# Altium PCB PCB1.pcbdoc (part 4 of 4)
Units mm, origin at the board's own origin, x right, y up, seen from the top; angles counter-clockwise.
Board outline 94.87 x 122.3 mm, 4 copper layers (Top Layer, Inner1, Inner2, Bottom Layer); 129 components, 127 nets, 714 pads, 326 vias.
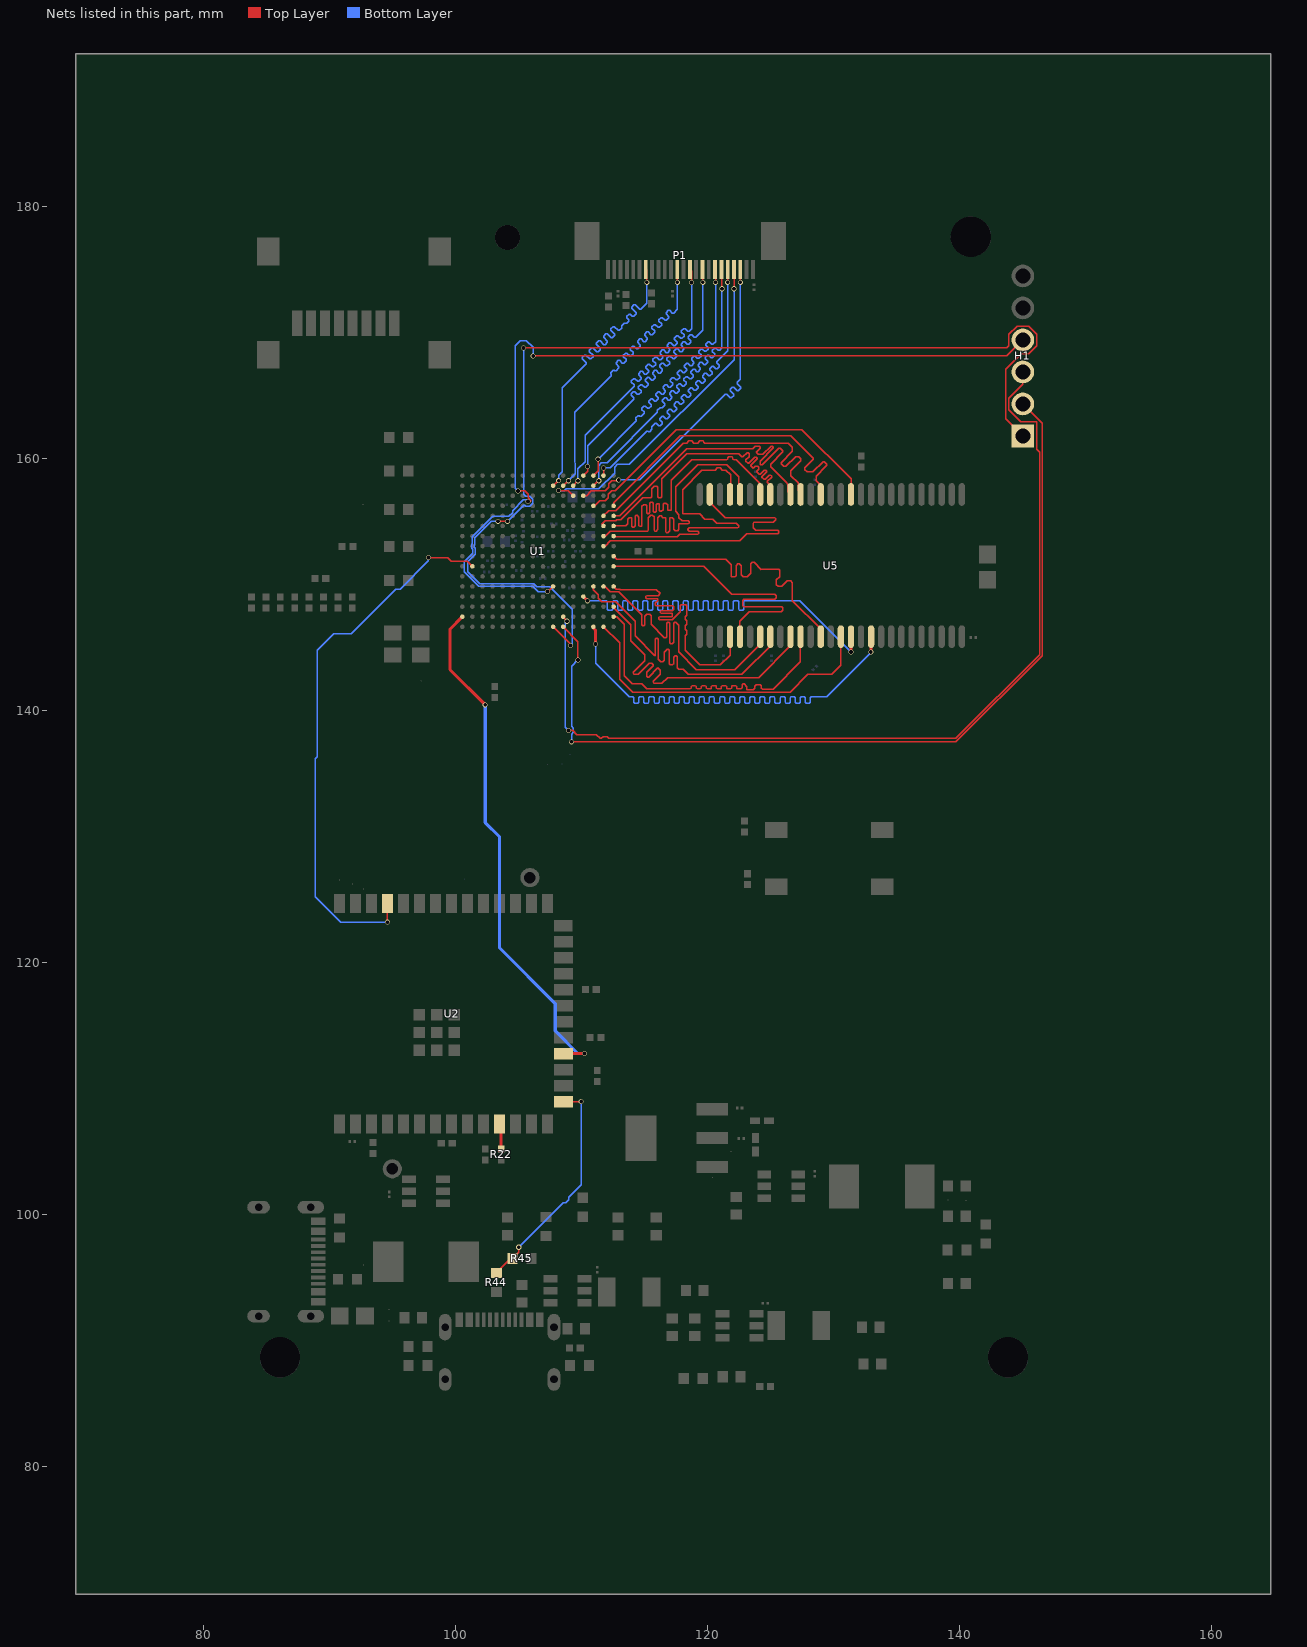
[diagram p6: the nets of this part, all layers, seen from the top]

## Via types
v1: diameter 0.4, hole 0.3, Top Layer to Bottom Layer, 311 vias
v2: diameter 1, hole 0.5, Top Layer to Bottom Layer, 12 vias
v3: diameter 0.5, hole 0.3, Top Layer to Bottom Layer, 3 vias

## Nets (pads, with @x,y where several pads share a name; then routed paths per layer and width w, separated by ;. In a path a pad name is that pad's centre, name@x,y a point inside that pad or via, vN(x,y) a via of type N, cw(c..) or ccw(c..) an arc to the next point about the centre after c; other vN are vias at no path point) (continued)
SD_DQ1: U1.M16 U5.4 | length 25
  Top Layer w0.1: U1.M16@112.553,149.854 112.769,149.638 113.03,149.638 113.068,149.6 115.957,149.6 116.258,149.299 116.087,149.127 115.189,149.127 115.118,149.056 115.118,148.956 115.189,148.886 116.036,148.886 116.078,148.844 116.078,148.705 115.88,148.508 115.88,148.408 115.951,148.337 117.22,148.337 117.327,148.23 117.327,148.061 117.2,147.934 116.332,147.934 116.267,147.869 116.267,147.777 116.332,147.713 117.22,147.713 117.22,147.479 117.203,147.461 116.205,147.461 116.134,147.391 116.134,147.291 116.205,147.22 117.22,147.22 117.856,147.856 117.856,148.336 117.927,148.407 118.293,148.407 118.364,148.336 118.364,147.574 118.237,147.447 118.237,147.243 118.357,147.123 118.357,146.843 118.237,146.723 118.237,146.443 118.357,146.323 118.357,146.043 118.237,145.923 118.237,144.78 119.38,143.637 121.031,143.637 121.794,144.4 U5.4@121.794,145.996
SD_DQ2: U1.K16 U5.5 | length 25.6
  Top Layer w0.1: U1.K16@112.553,151.454 119.691,151.454 121.92,149.225 125.349,149.225 125.476,149.098 125.476,148.971 125.333,148.828 122.901,148.828 122.791,148.717 122.791,148.313 122.851,148.253 125.913,148.253 125.984,148.182 125.984,147.955 125.858,147.829 123.318,147.829 122.577,147.088 122.577,146.267 122.594,146.25 U5.5@122.594,145.996
SD_DQ3: U1.M15 U5.7 | length 24.8
  Top Layer w0.1: U1.M15@111.753,149.854 111.833,149.854 111.847,149.839 111.895,149.839 112.298,149.436 112.946,149.436 114.793,147.589 114.793,146.812 114.863,146.741 114.963,146.741 115.034,146.812 115.034,147.489 115.189,147.644 115.443,147.644 115.543,147.544 115.543,146.839 116.586,145.796 116.713,145.796 116.771,145.854 116.771,146.939 116.842,147.01 116.942,147.01 117.012,146.939 117.012,145.37 117.094,145.288 117.221,145.288 117.345,145.412 117.345,146.939 117.404,146.998 117.487,146.998 117.709,146.776 117.709,144.673 119.126,143.256 122.179,143.256 124.05,145.127 124.05,145.725 124.067,145.742 124.067,145.869 U5.7@124.194,145.996
SD_DQ4: U1.M14 U5.8 | length 25.8
  Top Layer w0.1: U1.M14@110.953,149.854 110.953,149.594 111.335,149.212 111.335,148.932 111.631,148.636 112.711,148.636 114.273,147.074 114.273,145.923 115.831,144.365 115.863,144.397 115.863,145.669 115.934,145.74 116.034,145.74 116.104,145.669 116.104,144.092 116.305,143.891 116.459,143.891 116.578,144.01 116.578,144.632 116.796,144.851 116.896,144.851 116.967,144.78 116.967,143.737 117.067,143.637 117.221,143.637 117.313,143.729 117.313,144.225 117.431,144.343 117.531,144.343 117.602,144.272 117.602,143.405 117.729,143.278 118.069,143.278 118.472,142.875 122.743,142.875 125.151,145.283 125.151,145.839 U5.8@124.994,145.996
SD_DQ5: U1.P16 U5.10 | length 25.6
  Top Layer w0.1: U1.P16@112.553,148.254 112.553,148.145 113.898,146.8 113.898,145.563 115.032,144.429 115.032,143.975 114.102,143.046 114.102,142.946 114.173,142.875 114.493,142.875 115.382,143.764 115.57,143.764 115.697,143.637 115.697,143.571 115.176,143.051 115.176,142.735 115.247,142.665 115.347,142.665 116.072,143.389 116.241,143.22 116.241,142.898 115.69,142.347 115.69,142.247 115.761,142.176 116.395,142.176 116.84,142.621 124.071,142.621 126.594,145.144 U5.10@126.594,145.996
SD_DQ6: U1.R16 U5.11 | length 25.2
  Top Layer w0.1: U1.R16@112.553,147.454 112.817,147.454 113.411,146.86 113.411,142.748 114.042,142.117 114.804,142.117 115.205,141.716 118.647,141.716 118.717,141.787 118.717,141.915 118.788,141.986 119.047,141.986 119.117,141.915 119.117,141.787 119.188,141.716 119.447,141.716 119.517,141.787 119.517,141.915 119.588,141.986 119.847,141.986 119.917,141.915 119.917,141.787 119.988,141.716 120.247,141.716 120.317,141.787 120.317,141.915 120.388,141.986 120.647,141.986 120.717,141.915 120.717,141.787 120.788,141.716 121.047,141.716 121.117,141.787 121.117,141.915 121.188,141.986 121.447,141.986 121.517,141.915 121.517,141.787 121.588,141.716 121.847,141.716 121.917,141.787 121.917,141.915 121.988,141.986 122.247,141.986 122.317,141.915 122.317,141.787 122.388,141.716 122.665,141.716 122.765,141.816 122.765,142.042 122.836,142.113 122.936,142.113 123.142,141.907 123.142,141.656 123.654,141.656 123.754,141.756 123.754,141.915 123.881,142.042 124.206,142.042 124.277,141.972 124.277,141.786 124.377,141.686 125.208,141.686 127.381,143.859 U5.11@127.381,145.491
SD_DQ7: U1.J16 U5.13 | length 25.2
  Top Layer w0.1: U1.J16@112.553,152.254 112.788,152.019 121.44,152.019 121.876,151.582 121.876,150.68 121.947,150.609 122.188,150.609 122.288,150.709 122.288,151.511 122.425,151.647 122.546,151.647 122.684,151.509 122.684,150.774 122.849,150.609 123.177,150.609 123.46,150.892 123.46,151.654 123.571,151.765 123.714,151.765 124.282,151.197 124.286,151.201 125.659,151.201 125.73,151.13 125.73,150.631 125.476,150.377 125.476,150.003 125.619,149.86 125.916,149.86 126.351,150.296 126.619,150.296 126.748,150.166 126.748,148.732 ; 126.748,148.731 128.994,146.485 U5.13@128.994,145.996
SD_DQ8: U1.D16 U5.42 | length 25.2
  Top Layer w0.1: U1.D16@112.553,156.254 112.553,156.508 117.843,161.798 126.619,161.798 128.397,160.02 128.397,159.939 127.741,159.283 127.741,159.131 127.929,158.943 128.363,158.943 129.186,159.766 129.286,159.766 129.484,159.568 129.484,159.456 129.413,159.385 129.407,159.385 128.63,158.608 128.63,158.242 128.867,158.005 128.867,157.407 U5.42@128.994,157.28
SD_DQ9: U1.E15 U5.44 | length 25
  Top Layer w0.1: U1.E15@111.753,155.454 112.171,155.872 112.711,155.872 118.066,161.226 118.366,161.226 118.436,161.297 118.436,161.346 118.507,161.417 118.766,161.417 118.836,161.346 118.836,161.297 118.907,161.226 119.252,161.226 119.323,161.297 119.323,161.346 119.394,161.417 119.652,161.417 119.723,161.346 119.723,161.297 119.794,161.226 126.428,161.226 126.746,160.909 126.746,160.57 125.857,159.681 125.857,159.573 126.045,159.385 126.238,159.385 127,160.147 127.254,160.147 127.423,159.978 127.423,159.836 126.619,159.032 126.619,158.653 127.203,158.069 127.203,157.471 U5.44@127.394,157.28
SD_DQ10: U1.E16 U5.45 | length 25
  Top Layer w0.1: U1.E16@112.553,155.454 113.036,155.454 118.364,160.782 123.581,160.782 123.779,160.98 124.135,160.98 124.206,160.909 124.206,160.823 123.873,160.49 124.031,160.332 124.404,160.332 125.051,160.98 125.151,160.98 125.222,160.909 125.222,160.842 124.176,159.796 124.176,159.569 124.247,159.498 124.347,159.498 125.68,160.832 125.78,160.832 125.984,160.628 125.984,160.528 125.023,159.567 125.023,159.34 126.246,158.117 126.246,158.112 126.38,157.978 126.38,157.38 126.48,157.28 U5.45@126.594,157.28
SD_DQ11: U1.F15 U5.47 | length 25.1
  Top Layer w0.1: U1.F15@111.753,154.654 111.626,154.781 111.626,154.806 111.892,155.072 112.711,155.072 112.802,155.163 113.126,155.163 114.864,156.901 115.499,156.901 115.57,156.972 115.57,157.607 115.773,157.81 115.978,157.81 116.078,157.71 116.078,156.972 116.149,156.901 116.298,156.901 116.369,156.972 116.369,158.406 118.364,160.401 122.471,160.401 122.731,160.141 122.816,160.141 123.146,160.472 123.246,160.472 123.317,160.401 123.317,160.147 123.063,159.893 123.063,159.809 123.249,159.624 123.302,159.624 123.769,160.091 123.881,160.091 123.952,160.02 123.952,159.975 123.444,159.467 123.444,159.428 123.644,159.229 123.8,159.385 124.016,159.385 124.079,159.322 124.079,159.162 123.921,159.004 123.921,158.951 124.122,158.75 124.206,158.75 124.531,159.075 124.643,159.075 124.714,159.004 124.714,158.955 124.333,158.574 124.333,158.539 124.528,158.344 124.575,158.344 124.924,158.694 125.024,158.694 125.095,158.623 125.095,158.525 124.757,158.187 124.757,158.115 124.994,157.878 U5.47@124.994,157.28
SD_DQ12: U1.F16 U5.48 | length 25.1
  Top Layer w0.1: U1.F16@112.553,154.654 113.506,154.654 113.665,154.813 113.665,155.194 113.792,155.321 113.959,155.321 114.002,155.277 114.002,154.63 114.073,154.559 114.173,154.559 114.281,154.667 114.281,155.429 114.339,155.487 114.427,155.487 114.562,155.352 114.562,154.69 114.637,154.615 114.737,154.615 114.808,154.686 114.808,156.21 114.935,156.337 115.121,156.337 115.202,156.257 115.202,155.702 115.272,155.631 115.341,155.631 115.443,155.734 115.443,156.459 115.506,156.522 115.639,156.522 115.71,156.451 115.71,155.829 115.78,155.758 115.88,155.758 115.951,155.829 115.951,156.337 116.015,156.401 116.141,156.401 116.176,156.366 116.176,155.885 116.247,155.814 116.347,155.814 116.488,155.956 116.488,156.366 116.586,156.464 116.713,156.464 116.84,156.337 116.84,155.956 116.911,155.885 117.079,155.885 117.15,155.956 117.15,158.298 118.745,159.893 121.554,159.893 121.624,159.964 121.624,160.076 121.695,160.147 121.954,160.147 122.024,160.076 122.024,159.964 122.095,159.893 122.301,159.893 124.136,158.058 124.136,157.38 124.194,157.322 U5.48@124.194,157.28
SD_DQ13: U1.G15 U5.50 | length 25.1
  Top Layer w0.1: U1.G15@111.753,153.854 111.894,153.854 112.276,154.236 115.247,154.236 115.316,154.305 115.316,155.321 115.499,155.504 115.641,155.504 115.768,155.377 115.768,154.305 115.838,154.234 115.938,154.234 116.078,154.374 116.078,155.321 116.205,155.448 116.332,155.448 116.459,155.321 116.675,155.321 116.675,154.178 116.746,154.107 116.846,154.107 117.005,154.267 117.005,155.264 117.062,155.321 117.221,155.321 117.348,155.194 117.348,154.378 117.448,154.278 117.629,154.278 117.729,154.378 117.729,154.771 117.771,154.813 118.491,154.813 118.562,154.884 118.562,154.984 118.483,155.062 117.988,155.062 117.729,155.321 117.729,155.562 117.487,155.805 117.487,157.752 119.247,159.512 121.539,159.512 122.476,158.575 122.476,157.399 U5.50@122.594,157.28
SD_DQ14: U1.G16 U5.51 | length 25
  Top Layer w0.1: U1.G16@112.553,153.854 112.616,153.79 117.595,153.79 117.789,153.984 119.253,153.984 119.324,154.055 119.324,154.155 119.253,154.225 118.571,154.225 118.458,154.338 118.458,154.399 118.553,154.494 122.428,154.494 122.499,154.564 122.499,154.664 122.279,154.884 120.733,154.884 120.423,155.194 119.799,155.194 119.38,155.613 118.03,155.613 118.03,157.527 119.57,159.067 120.634,159.067 120.705,159.138 120.705,159.212 120.775,159.283 121.034,159.283 121.105,159.212 121.105,159.138 121.176,159.067 121.475,159.067 121.84,158.703 121.84,157.615 U5.51@121.858,157.598
SD_DQ15: U1.H15 U5.53 | length 25.3
  Top Layer w0.1: U1.H15@111.753,153.054 111.88,153.054 112.298,153.472 122.584,153.472 123.141,154.029 125.569,154.029 125.674,154.134 125.674,154.234 125.603,154.305 123.825,154.305 123.627,154.503 123.627,154.869 123.698,154.94 125.209,154.94 125.42,155.15 125.42,155.25 125.349,155.321 121.412,155.321 120.321,156.412 U5.53@120.321,157.153
SD_DQM0: U1.T15 U5.15 | length 25.8
  Top Layer w0.1: U1.T15@111.753,146.654 113.03,145.377 113.03,142.494 114.068,141.456 126.563,141.456 127.982,142.875 129.881,142.875 130.594,143.588 U5.15@130.594,145.869
SD_DQM1: U1.D14 U5.39 | length 25.9
  Top Layer w0.1: U1.D14@110.953,156.254 111.042,156.254 111.46,156.672 111.911,156.672 112.135,156.896 112.135,157.176 112.395,157.436 112.675,157.436 117.545,162.306 127.492,162.306 131.403,158.396 131.403,157.407 U5.39@131.276,157.28
SD_RAS_N: U1.T14 U5.18 | length 43.8
  Top Layer w0.254: U1.T14@110.998,146.488 111.125,146.361 v1(111.125,145.288) ; v1(132.969,144.653) 132.994,144.678 U5.18@132.994,145.869
  Bottom Layer w0.1: v1(111.125,145.288) 111.125,143.764 113.792,141.097 114.092,141.097 114.163,141.026 114.163,140.66 114.233,140.589 114.492,140.589 114.563,140.66 114.563,141.026 114.633,141.097 114.892,141.097 114.963,141.026 114.963,140.66 115.033,140.589 115.292,140.589 115.363,140.66 115.363,141.026 115.433,141.097 115.692,141.097 115.763,141.026 115.763,140.66 115.833,140.589 116.092,140.589 116.163,140.66 116.163,141.026 116.233,141.097 116.492,141.097 116.563,141.026 116.563,140.66 116.633,140.589 116.892,140.589 116.963,140.66 116.963,141.026 117.033,141.097 117.292,141.097 117.363,141.026 117.363,140.66 117.433,140.589 117.692,140.589 117.763,140.66 117.763,141.026 117.833,141.097 118.092,141.097 118.163,141.026 118.163,140.66 118.233,140.589 118.492,140.589 118.563,140.66 118.563,141.026 118.633,141.097 118.892,141.097 118.963,141.026 118.963,140.66 119.033,140.589 119.292,140.589 119.363,140.66 119.363,141.026 119.433,141.097 119.692,141.097 119.763,141.026 119.763,140.66 119.833,140.589 120.092,140.589 120.163,140.66 120.163,141.026 120.233,141.097 120.492,141.097 120.563,141.026 120.563,140.66 120.633,140.589 120.892,140.589 120.963,140.66 120.963,141.026 121.033,141.097 121.292,141.097 121.363,141.026 121.363,140.66 121.433,140.589 121.692,140.589 121.763,140.66 121.763,141.026 121.833,141.097 122.092,141.097 122.163,141.026 122.163,140.66 122.233,140.589 122.492,140.589 122.563,140.66 122.563,141.026 122.633,141.097 122.892,141.097 122.963,141.026 122.963,140.66 123.033,140.589 123.292,140.589 123.363,140.66 123.363,141.026 123.433,141.097 123.692,141.097 123.763,141.026 123.763,140.66 123.833,140.589 124.092,140.589 124.163,140.66 124.163,141.026 124.233,141.097 124.492,141.097 124.563,141.026 124.563,140.66 124.633,140.589 124.892,140.589 124.963,140.66 124.963,141.026 125.033,141.097 125.292,141.097 125.363,141.026 125.363,140.66 125.433,140.589 125.692,140.589 125.763,140.66 125.763,141.026 125.833,141.097 126.092,141.097 126.163,141.026 126.163,140.66 126.233,140.589 126.492,140.589 126.563,140.66 126.563,141.026 126.633,141.097 126.892,141.097 126.963,141.026 126.963,140.66 127.033,140.589 127.292,140.589 127.363,140.66 127.363,141.026 127.433,141.097 127.692,141.097 127.763,141.026 127.763,140.66 127.833,140.589 128.092,140.589 128.163,140.66 128.163,141.026 128.233,141.097 129.461,141.097 132.969,144.605 v1(132.969,144.653)
SD_WE_N: U1.N13 U5.16 | length 43.3
  Top Layer w0.254: U1.N13@110.153,149.054 v1(110.49,148.717) ; v1(131.394,144.653) U5.16@131.394,145.869
  Bottom Layer w0.1: v1(110.49,148.717) 111.998,148.717 112.069,148.646 112.069,148.026 112.14,147.955 112.398,147.955 112.469,148.026 112.469,148.646 112.54,148.717 112.798,148.717 112.869,148.646 112.869,148.026 112.94,147.955 113.198,147.955 113.269,148.026 113.269,148.646 113.34,148.717 113.598,148.717 113.669,148.646 113.669,148.026 113.74,147.955 113.998,147.955 114.069,148.026 114.069,148.646 114.14,148.717 114.398,148.717 114.469,148.646 114.469,148.026 114.54,147.955 114.798,147.955 114.869,148.026 114.869,148.646 114.94,148.717 115.198,148.717 115.269,148.646 115.269,148.026 115.34,147.955 115.598,147.955 115.669,148.026 115.669,148.646 115.74,148.717 115.998,148.717 116.069,148.646 116.069,148.026 116.14,147.955 116.398,147.955 116.469,148.026 116.469,148.646 116.54,148.717 116.798,148.717 116.869,148.646 116.869,148.026 116.94,147.955 117.198,147.955 117.269,148.026 117.269,148.646 117.34,148.717 117.598,148.717 117.669,148.646 117.669,148.026 117.74,147.955 117.998,147.955 118.069,148.026 118.069,148.646 118.14,148.717 118.398,148.717 118.469,148.646 118.469,148.026 118.54,147.955 118.798,147.955 118.869,148.026 118.869,148.646 118.94,148.717 119.198,148.717 119.269,148.646 119.269,148.026 119.34,147.955 119.598,147.955 119.669,148.026 119.669,148.646 119.74,148.717 119.998,148.717 120.069,148.646 120.069,148.026 120.14,147.955 120.398,147.955 120.469,148.026 120.469,148.646 120.54,148.717 120.798,148.717 120.869,148.646 120.869,148.026 120.94,147.955 121.198,147.955 121.269,148.026 121.269,148.646 121.34,148.717 121.598,148.717 121.669,148.646 121.669,148.026 121.74,147.955 121.998,147.955 122.069,148.026 122.069,148.646 122.14,148.717 122.398,148.717 122.469,148.646 122.469,148.026 122.54,147.955 122.798,147.955 122.869,148.026 122.869,148.646 122.94,148.717 127.33,148.717 v1(131.394,144.653)
SDA: R22.1 U2.11 | length 1.9
  Top Layer w0.254: R22.1@103.627,105.283 U2.11@103.627,107.201
SSPI_CS_N: U1.R1 U2.18 | length 41.3
  Top Layer w0.254: U1.R1@100.553,147.454 99.568,146.469 99.568,143.256 v1(102.362,140.462) ; U2.18@108.717,112.776 v1(110.236,112.776)
  Bottom Layer w0.254: v1(102.362,140.462) 102.362,131.108 103.505,129.965 103.505,121.158 107.923,116.74 107.923,114.581 109.728,112.776 v1(110.236,112.776)
TCK: H1.1 U1.T10 | length 88.4
  Top Layer w0.1: v1(103.374,155.026) 103.585,155.026 103.595,155.036 103.911,155.036 103.921,155.026 104.099,155.026 v1@104.14,155.067 ; v1(105.41,168.783) 143.748,168.783 143.932,168.967 143.932,169.874 144.578,170.52 145.49,170.52 146.136,169.874 146.136,168.962 145.49,168.316 144.914,168.316 143.681,167.084 143.681,163.151 H1.1@145.034,161.798 ; U1.T10@107.753,146.654 109.137,145.27 v1(109.137,145.161)
  Bottom Layer w0.1: v1(103.374,155.026) 102.858,155.026 101.555,153.723 101.555,153.167 101.506,153.117 101.506,152.965 101.567,152.903 101.567,152.405 100.965,151.803 100.965,151.032 101.937,150.06 106.236,150.06 106.449,149.846 107.482,149.846 109.268,148.06 109.268,145.292 v1(109.137,145.161) ; v1(104.14,155.026) 105.41,156.296 105.495,156.296 105.587,156.204 105.92,156.204 106.155,156.44 106.155,156.773 105.92,157.008 105.587,157.008 105.41,157.185 v1(105.41,168.783)
TDI: H1.3 U1.R11 | length 74.5
  Top Layer w0.1: U1.R11@108.553,147.454 108.553,147.406 v1(108.866,147.093) ; v1(108.966,138.43) 109.294,138.43 109.621,138.103 111.171,138.103 111.479,137.795 111.593,137.795 111.72,137.922 112.054,137.922 112.181,137.795 139.7,137.795 146.358,144.453 146.358,160.518 146.145,160.731 146.145,162.944 144.869,162.944 143.932,163.882 143.932,164.794 145.034,165.896 H1.3@145.034,166.878
  Bottom Layer w0.1: v1(108.866,147.093) 108.735,146.962 108.735,138.661 v1(108.966,138.43)
TDO: H1.4 U1.M10 | length 72.1
  Top Layer w0.1: v1(104.965,157.419) 105.177,157.419 105.195,157.436 105.511,157.436 105.771,157.176 105.771,156.896 105.995,156.672 105.995,156.636 105.965,156.606 v1(105.753,156.606) ; v1(106.172,168.148) 143.764,168.148 H1.4@145.034,169.418 ; v1(107.315,149.444) 107.343,149.444 U1.M10@107.753,149.854
  Bottom Layer w0.1: v1(104.965,157.419) 104.754,157.63 104.754,168.966 105.154,169.366 105.635,169.366 106.172,168.829 v1(106.172,168.148) ; v1(105.753,156.606) 105.626,156.733 105.397,156.733 104.542,155.879 104.542,155.722 104.248,155.428 102.977,155.428 101.355,153.806 101.355,153.249 101.306,153.2 101.306,152.882 101.367,152.821 101.367,152.487 100.711,151.831 100.711,151.003 101.854,149.86 106.153,149.86 106.568,149.444 v1(107.315,149.444)
TMS: H1.2 U1.T11 | length 70.7
  Top Layer w0.1: U1.T11@108.553,146.654 109.728,145.479 v1(109.728,144.018) ; v1(109.22,137.52) 139.708,137.52 146.558,144.37 146.558,162.814 H1.2@145.034,164.338
  Bottom Layer w0.1: v1(109.22,137.52) 109.22,138.115 109.368,138.263 109.368,138.597 109.22,138.745 109.22,143.51 v1(109.728,144.018)
TX: U1.K2 U2.37 | length 43.6
  Top Layer w0.1: v1@94.61,123.19 U2.37@94.61,124.701 ; v1@97.79,152.146 99.38,152.146 99.655,151.871 100.934,151.871 ; 100.935,151.872 U1.K2@101.353,151.454
  Bottom Layer w0.1: v1(94.61,123.211) 90.911,123.211 88.877,125.245 88.877,136.174 89.027,136.324 89.027,144.78 90.351,146.104 91.723,146.104 95.258,149.639 95.626,149.639 97.865,151.878 v1(97.865,152.146)
USB_VBUS: R44.1 R45.2 U2.15 | length 18
  Top Layer w0.1: R44.1@103.251,95.368 104.403,96.52 R45.2@104.53,96.52 105.029,97.019 v1(105.029,97.409) ; U2.15@108.59,108.966 v1(109.982,108.966)
  Bottom Layer w0.1: v1(105.029,97.409) 108.555,100.935 108.752,100.935 108.987,101.171 108.987,101.367 109.982,102.362 v1(109.982,108.966)
VSYNC: P1.7 U1.B10 | length 27.1
  Top Layer w0.1: U1.B10@107.753,157.854 108.149,158.25 v1(108.196,158.25) ; P1.7@115.11,175.02 115.189,174.942 v1(115.189,173.99)
  Bottom Layer w0.1: v1(108.196,158.25) 108.196,158.682 108.479,158.964 108.479,165.629 110.374,167.524 110.374,167.624 110.065,167.933 110.065,168.033 110.248,168.216 110.348,168.216 110.657,167.907 110.757,167.907 110.94,168.09 110.94,168.19 110.631,168.499 110.631,168.599 110.813,168.782 110.913,168.782 111.223,168.473 111.323,168.473 111.505,168.655 111.505,168.755 111.196,169.065 111.196,169.165 111.379,169.347 111.479,169.347 111.788,169.038 111.888,169.038 112.071,169.221 112.071,169.321 111.762,169.63 111.762,169.73 111.945,169.913 112.045,169.913 112.354,169.604 112.454,169.604 112.637,169.787 112.637,169.887 112.328,170.196 112.328,170.296 112.511,170.479 112.611,170.479 112.92,170.17 113.02,170.17 113.206,170.356 113.206,170.549 113.393,170.735 113.585,170.735 113.768,170.918 113.768,171.018 113.602,171.184 113.602,171.284 113.785,171.467 113.885,171.467 114.051,171.301 114.151,171.301 114.334,171.484 114.334,171.584 113.989,171.928 113.989,172.028 114.172,172.211 114.272,172.211 114.617,171.867 114.717,171.867 115.189,172.339 v1(115.189,173.99)
Y2: P1.19 U1.B14 | length 27
  Top Layer w0.1: U1.B14@110.953,157.854 111.341,158.242 v1(111.379,158.242) ; P1.19@121.11,175.02 121.158,174.972 v1(121.158,173.482)
  Bottom Layer w0.1: v1(111.379,158.242) 111.379,159.07 111.358,159.091 111.358,159.425 111.593,159.66 112.035,159.66 116.039,163.664 116.039,163.83 116.24,164.03 116.405,164.03 116.621,164.246 116.621,164.346 116.433,164.534 116.433,164.634 116.615,164.816 116.715,164.816 116.903,164.628 117.003,164.628 117.186,164.811 117.186,164.911 116.998,165.099 116.998,165.199 117.181,165.382 117.281,165.382 117.469,165.194 117.569,165.194 117.752,165.377 117.752,165.477 117.564,165.665 117.564,165.765 117.747,165.948 117.847,165.948 118.035,165.76 118.135,165.76 118.318,165.943 118.318,166.043 118.13,166.231 118.13,166.331 118.313,166.513 118.413,166.513 118.601,166.326 118.701,166.326 118.883,166.508 118.883,166.608 118.695,166.796 118.695,166.896 118.878,167.079 118.978,167.079 119.166,166.891 119.266,166.891 119.449,167.074 119.449,167.174 119.261,167.362 119.261,167.462 119.444,167.645 119.544,167.645 119.732,167.457 119.832,167.457 120.015,167.64 120.015,167.74 119.827,167.928 119.827,168.028 120.01,168.211 120.11,168.211 120.298,168.023 120.398,168.023 120.58,168.205 120.58,168.305 120.392,168.493 120.392,168.593 120.575,168.776 120.675,168.776 120.863,168.588 120.963,168.588 121.158,168.783 v1(121.158,173.482)
Y3: P1.21 U1.C12 | length 27
  Top Layer w0.1: v1(108.19,157.465) 108.942,157.465 U1.C12@109.353,157.054 ; v1(122.112,173.482) P1.21@122.112,175.017
  Bottom Layer w0.1: v1(108.19,157.465) 108.639,157.465 108.798,157.624 111.396,157.624 112.628,158.856 112.628,159.298 112.863,159.533 113.813,159.533 122.112,167.832 v1(122.112,173.482)
Y4: P1.22 U1.C13 | length 27
  Top Layer w0.1: U1.C13@110.153,157.054 110.413,157.054 110.795,157.436 111.875,157.436 112.171,157.732 112.171,158.012 112.395,158.236 112.887,158.236 v1(112.962,158.31) ; v1(122.612,173.99) P1.22@122.612,175.017
  Bottom Layer w0.1: v1(112.962,158.31) 114.622,158.31 121.417,165.105 121.517,165.105 121.798,164.824 121.898,164.824 122.081,165.007 122.081,165.107 121.8,165.388 121.8,165.488 121.983,165.671 122.083,165.671 122.364,165.39 122.464,165.39 122.647,165.573 122.647,165.673 122.366,165.954 122.366,166.054 122.612,166.3 v1(122.612,173.99)
Y5: P1.20 U1.A15 | length 27
  Top Layer w0.1: U1.A15@111.753,158.654 111.76,158.661 v1(111.76,159.258) ; v1(121.612,173.99) P1.20@121.612,175.017
  Bottom Layer w0.1: v1(111.76,159.258) 112.306,159.258 115.203,162.156 115.303,162.156 115.311,162.147 115.411,162.147 115.594,162.33 115.594,162.43 115.586,162.439 115.586,162.539 115.846,162.799 115.946,162.799 116.145,162.6 116.245,162.6 116.428,162.783 116.428,162.883 116.229,163.082 116.229,163.182 116.412,163.364 116.512,163.364 116.711,163.166 116.811,163.166 116.994,163.349 116.994,163.449 116.795,163.647 116.795,163.747 116.978,163.93 117.078,163.93 117.276,163.731 117.376,163.731 117.559,163.914 117.559,164.014 117.361,164.213 117.361,164.313 117.543,164.496 117.643,164.496 117.842,164.297 117.942,164.297 118.125,164.48 118.125,164.58 117.926,164.779 117.926,164.879 118.109,165.061 118.209,165.061 118.408,164.863 118.508,164.863 118.691,165.046 118.691,165.146 118.492,165.344 118.492,165.444 118.675,165.627 118.775,165.627 118.973,165.428 119.073,165.428 119.256,165.611 119.256,165.711 119.058,165.91 119.058,166.01 119.24,166.193 119.34,166.193 119.539,165.994 119.639,165.994 119.822,166.177 119.822,166.277 119.623,166.476 119.623,166.576 119.806,166.758 119.906,166.758 120.105,166.56 120.205,166.56 120.388,166.743 120.388,166.843 120.189,167.041 120.189,167.141 120.372,167.324 120.472,167.324 120.67,167.125 120.77,167.125 120.953,167.308 120.953,167.408 120.755,167.607 120.755,167.707 121.612,168.564 v1(121.612,173.99)
Y6: P1.18 U1.A14 | length 27.1
  Top Layer w0.1: U1.A14@110.953,158.654 111.318,159.019 v1(111.318,159.954) ; P1.18@120.61,175.02 120.65,174.98 v1(120.65,173.99)
  Bottom Layer w0.1: v1(111.318,159.954) 114.357,162.992 114.357,163.092 114.311,163.137 114.311,163.237 114.494,163.42 114.594,163.42 114.64,163.375 114.74,163.375 114.969,163.604 114.969,163.704 114.783,163.889 114.783,163.989 114.966,164.172 115.066,164.172 115.251,163.986 115.351,163.986 115.534,164.169 115.534,164.269 115.349,164.455 115.349,164.555 115.532,164.737 115.632,164.737 115.817,164.552 115.917,164.552 116.1,164.735 116.1,164.835 115.915,165.02 115.915,165.12 116.097,165.303 116.197,165.303 116.383,165.118 116.483,165.118 116.666,165.301 116.666,165.401 116.48,165.586 116.48,165.686 116.663,165.869 116.763,165.869 116.948,165.683 117.048,165.683 117.231,165.866 117.231,165.966 117.046,166.152 117.046,166.252 117.229,166.435 117.329,166.435 117.514,166.249 117.614,166.249 117.797,166.432 117.797,166.532 117.612,166.717 117.612,166.817 117.794,167 117.894,167 118.08,166.815 118.18,166.815 118.363,166.998 118.363,167.098 118.177,167.283 118.177,167.383 118.36,167.566 118.46,167.566 118.645,167.381 118.745,167.381 118.928,167.563 118.928,167.663 118.743,167.849 118.743,167.949 118.926,168.132 119.026,168.132 119.211,167.946 119.311,167.946 119.494,168.129 119.494,168.229 119.309,168.414 119.309,168.514 119.492,168.697 119.592,168.697 119.777,168.512 119.877,168.512 120.06,168.695 120.06,168.795 119.874,168.98 119.874,169.08 120.057,169.263 120.157,169.263 120.343,169.078 120.443,169.078 120.65,169.285 v1(120.65,173.99)
Y7: P1.16 U1.A13 | length 26.9
  Top Layer w0.1: U1.A13@110.153,158.654 110.49,158.991 v1(110.49,159.385) ; P1.16@119.61,175.019 119.634,174.995 v1(119.634,173.99)
  Bottom Layer w0.1: v1(110.49,159.385) 110.49,161.036 114.168,164.714 114.168,164.814 113.951,165.032 113.951,165.132 114.133,165.314 114.233,165.314 114.451,165.097 114.551,165.097 114.734,165.28 114.734,165.38 114.516,165.597 114.516,165.697 114.699,165.88 114.799,165.88 115.017,165.663 115.117,165.663 115.299,165.845 115.299,165.945 115.082,166.163 115.082,166.263 115.265,166.446 115.365,166.446 115.582,166.228 115.682,166.228 115.865,166.411 115.865,166.511 115.648,166.729 115.648,166.829 115.83,167.011 115.93,167.011 116.148,166.794 116.248,166.794 116.431,166.977 116.431,167.077 116.213,167.294 116.213,167.394 116.396,167.577 116.496,167.577 116.714,167.36 116.814,167.36 116.996,167.542 116.996,167.642 116.779,167.86 116.779,167.96 116.962,168.143 117.062,168.143 117.279,167.925 117.379,167.925 117.562,168.108 117.562,168.208 117.345,168.426 117.345,168.526 117.527,168.708 117.627,168.708 117.845,168.491 117.945,168.491 118.128,168.674 118.128,168.774 117.91,168.991 117.91,169.091 118.093,169.274 118.193,169.274 118.411,169.057 118.511,169.057 118.693,169.239 118.693,169.339 118.476,169.557 118.476,169.657 118.659,169.84 118.759,169.84 118.976,169.622 119.076,169.622 119.634,170.18 v1(119.634,173.99)
Y8: P1.14 U1.B12 | length 27
  Top Layer w0.1: U1.B12@109.353,157.854 109.728,158.229 v1(109.728,158.242) ; P1.14@118.611,175.02 118.741,174.889 v1(118.741,173.986)
  Bottom Layer w0.1: v1(109.728,158.242) 109.728,159.192 110.29,159.754 110.29,161.852 114.188,165.75 114.188,165.85 113.97,166.067 113.97,166.167 114.153,166.35 114.253,166.35 114.471,166.133 114.571,166.133 114.764,166.326 114.764,166.426 114.547,166.644 114.547,166.744 114.73,166.927 114.83,166.927 115.047,166.709 115.147,166.709 115.33,166.892 115.33,166.992 115.112,167.209 115.112,167.309 115.295,167.492 115.395,167.492 115.613,167.275 115.713,167.275 115.896,167.458 115.896,167.558 115.678,167.775 115.678,167.875 115.861,168.058 115.961,168.058 116.178,167.84 116.278,167.84 116.461,168.023 116.461,168.123 116.244,168.341 116.244,168.441 116.427,168.624 116.527,168.624 116.744,168.406 116.844,168.406 117.027,168.589 117.027,168.689 116.809,168.906 116.809,169.006 116.992,169.189 117.092,169.189 117.31,168.972 117.41,168.972 117.593,169.155 117.593,169.255 117.375,169.472 117.375,169.572 117.558,169.755 117.658,169.755 117.876,169.538 117.976,169.538 118.158,169.72 118.158,169.82 117.941,170.038 117.941,170.138 118.124,170.321 118.224,170.321 118.441,170.103 118.541,170.103 118.741,170.303 v1(118.741,173.986)
Y9: P1.12 U1.B11 | length 27
  Top Layer w0.1: U1.B11@108.553,157.854 108.941,158.242 v1(108.966,158.242) ; v1(117.611,173.99) P1.12@117.611,175.02
  Bottom Layer w0.1: v1(108.966,158.242) 109.528,158.804 109.528,159.651 109.453,159.726 109.453,163.682 112.365,166.594 112.365,166.694 112.338,166.721 112.338,166.821 112.521,167.004 112.621,167.004 112.648,166.977 112.748,166.977 112.974,167.203 112.974,167.303 112.757,167.521 112.757,167.621 112.94,167.804 113.04,167.804 113.257,167.586 113.357,167.586 113.54,167.769 113.54,167.869 113.322,168.086 113.322,168.186 113.505,168.369 113.605,168.369 113.823,168.152 113.923,168.152 114.106,168.335 114.106,168.435 113.888,168.652 113.888,168.752 114.071,168.935 114.171,168.935 114.389,168.718 114.489,168.718 114.671,168.9 114.671,169 114.454,169.218 114.454,169.318 114.637,169.501 114.737,169.501 114.954,169.283 115.054,169.283 115.237,169.466 115.237,169.566 115.02,169.784 115.02,169.884 115.202,170.066 115.302,170.066 115.52,169.849 115.62,169.849 115.803,170.032 115.803,170.132 115.585,170.349 115.585,170.449 115.768,170.632 115.868,170.632 116.086,170.415 116.186,170.415 116.368,170.597 116.368,170.697 116.151,170.915 116.151,171.015 116.334,171.198 116.434,171.198 116.651,170.98 116.751,170.98 116.934,171.163 116.934,171.263 116.717,171.481 116.717,171.581 116.899,171.763 116.999,171.763 117.217,171.546 117.317,171.546 117.611,171.84 v1(117.611,173.99)
pads on no net: P1.1 P1.10 SCREW1.1 SCREW2.1 SCREW3.1 SCREW4.1 U1.A9 U1.B3 U1.B8 U1.B13 U1.B15 U1.B16 U1.C1 U1.C2 U1.C3 U1.C4 U1.C5 U1.C6 U1.C9 U1.C10 U1.C11 U1.C14 U1.C15 U1.C16 U1.D1 U1.D3 U1.D4 U1.D5 U1.D6 U1.D7 U1.D8 U1.D9 U1.D10 U1.D11 U1.D12 U1.D13 U1.E3 U1.E4 U1.E5 U1.E6 U1.E7 U1.E8 U1.E9 U1.E10 U1.E11 U1.E12 U1.E13 U1.E14 U1.F3 U1.F4 U1.F5 U1.F12 U1.F13 U1.F14 U1.G3 U1.G4 U1.G5 U1.G12 U1.G13 U1.G14 U1.H2 U1.H3 U1.H4 U1.H5 U1.H12 U1.H13 U1.H14 U1.J3 U1.J4 U1.J5 U1.J12 U1.J13 U1.K3 U1.K4 U1.K5 U1.K13 U1.K14 U1.K15 U1.L1 U1.L2 U1.L3 U1.L4 U1.L5 U1.L13 U1.L14 U1.L16 U1.M2 U1.M3 U1.M4 U1.M5 U1.M6 U1.M7 U1.M9 U1.M11 U1.M12 U1.M13 U1.N1 U1.N3 U1.N4 U1.N5 U1.N6 U1.N7 U1.N8 U1.N9 U1.N11 U1.N12 U1.N14 U1.N16 U1.P1 U1.P2 U1.P3 U1.P4 U1.P5 U1.P6 U1.P7 U1.P8 U1.P11 U1.P12 U1.P13 U1.P14 U1.P15 U1.R2 U1.R3 U1.R4 U1.R5 U1.R6 U1.R7 U1.R8 U1.R12 U1.R14 U1.T13 U2.4 U2.16 U2.26 U2.28 U2.29 U2.30 U2.32 U2.33 U2.34 U2.35 U2.38 U2.39 U5.40 U8.4 USB1.A6 USB1.A7 USB1.A8 USB1.B6 USB1.B7 USB1.B8 USB2.A8 USB2.B6 USB2.B7 USB2.B8
copper on no net: | length 20.4
  Top Layer w0.1: 91.821,126.238 92.07,125.989 92.07,124.701 ; 92.71,125.857 93.34,125.227 93.34,124.701 ; 94.61,107.201 94.839,106.972 v1(94.839,105.567) ; 103.5,124.701 103.5,125.336 105.037,126.873 105.664,126.873 105.918,126.619 ; v1(108.205,147.954) 108.254,147.955 108.553,148.254
  Top Layer w0.254: v1(99.695,148.286) 100.521,148.286 100.553,148.254 ; v1(99.867,150.794) 100.006,150.654 100.553,150.654 ; v1(99.949,149.098) 100.509,149.098 100.553,149.054 ; v1(100.95,148.699) 101.353,148.295 101.353,148.254 ; v1(101.748,148.611) 101.748,148.649 102.153,149.054 ; v1(102.505,147.854) 102.553,147.854 102.953,148.254 ; v1(102.616,148.717) 102.953,149.054 ; v1@103.355,147.805 103.355,147.856 103.753,148.254 ; v1(103.378,148.717) 103.416,148.717 103.753,149.054 ; v1@104.14,148.717 104.216,148.717 104.553,149.054 ; v1(104.221,147.874) 104.553,148.206 104.553,148.254 ; v1@104.902,148.59 104.902,148.603 105.353,149.054
  Bottom Layer w0.1: v1(94.839,105.567) 94.996,105.41 94.996,103.632 ; v1(98.679,150.666) 99.739,150.666 v1(99.867,150.794) ; v1(108.205,147.954) 108.585,147.574 108.585,147.447
  other v1: 103.353,147.807 104.936,148.624 104.154,148.703

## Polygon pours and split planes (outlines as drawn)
+3V3 on Inner2 (solid, remove dead copper): 76.2,185.674 158.369,185.674 158.369,76.2 76.2,76.2
GND on Inner1 (solid, remove dead copper): 77.597,185.801 152.654,185.801 152.654,81.661 77.597,81.661

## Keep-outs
Board Outline Layer:
  lines w0.254: 82.931,85.594 146.931,85.594 146.931,180.594 82.931,180.594 82.931,85.594

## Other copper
Top Layer:
  region net GND: 90.549,126.761 91.057,126.761 91.057,126.36 90.543,126.36 90.549,126.365
  region net GND: 92.459,96.213 92.967,96.213 92.967,95.811 92.453,95.811 92.459,95.817
  region net GND: 94.491,91.768 94.999,91.768 94.999,91.366 94.485,91.366 94.491,91.372
  region net +5V: 94.472,92.676 94.98,92.676 94.98,92.274 94.466,92.274 94.472,92.28
  region net +1V8: 121.619,105.193 122.127,105.193 122.127,104.791 121.614,104.791 121.619,104.796
  region net GND: 120.138,103.162 120.646,103.162 120.646,102.761 120.133,102.761 120.138,102.766
  region net GND: 140.255,101.322 140.763,101.322 140.763,100.921 140.25,100.921 140.255,100.926
  region net +3V3: 92.428,156.559 92.936,156.559 92.936,156.158 92.423,156.158 92.428,156.163
  region net GND: 97.031,142.568 97.539,142.568 97.539,142.166 97.025,142.166 97.031,142.172
  region net +1V1: 138.855,101.361 139.363,101.361 139.363,100.96 138.85,100.96 138.855,100.965
  region: 91.57,126.439 92.078,126.439 92.078,126.037 91.564,126.037 91.57,126.043
  region: 92.459,126.058 92.967,126.058 92.967,125.656 92.453,125.656 92.459,125.662
Bottom Layer:
  region net DONE: 108.842,136.726 109.35,136.726 109.35,136.324 108.836,136.324 108.842,136.33
  region net PROGRAMN: 107.064,135.942 107.572,135.942 107.572,135.541 107.058,135.541 107.064,135.546
  region net INITN: 100.46,126.82 100.968,126.82 100.968,126.418 100.454,126.418 100.46,126.424
  region net GND: 108.207,135.964 108.715,135.964 108.715,135.562 108.201,135.562 108.207,135.568
  region: 108.267,147.622 108.707,147.876 108.908,147.529 108.463,147.272 108.465,147.279

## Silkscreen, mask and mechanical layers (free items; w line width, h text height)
Top Silkscreen Layer:
  text "JTAG" at 143.15,165.691 h3.05 r90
